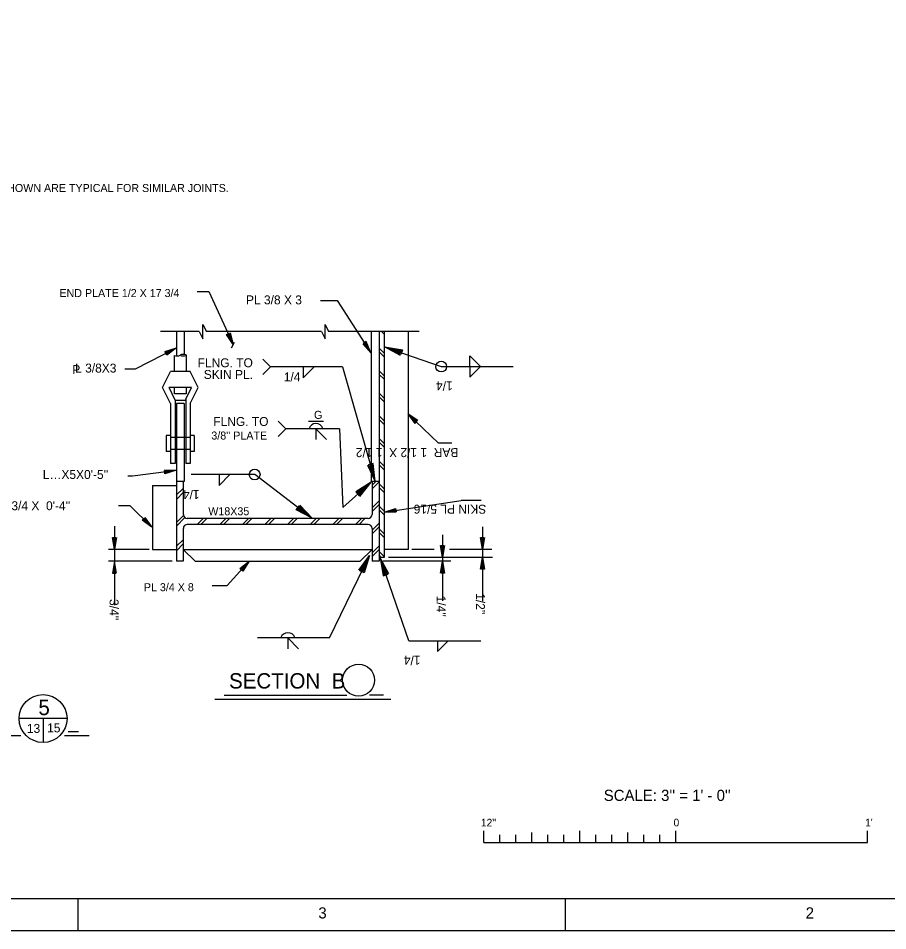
# Model space of a CAD drawing. Extents: x 0 to 13.3, y 0 to 9.3.
# Drawn here: x 5.231 to 9.766, y 0 to 4.76 of the extents above; entities that cross this region are included whole.
import ezdxf

# ---------------------------------------------------------------- set-up
doc = ezdxf.new("R2010")
doc.units = 0
for name, color, linetype in [('Level 1', 7, 'Continuous'), ('Level 10', 7, 'Continuous'), ('Level 13', 7, 'Continuous'), ('Level 2', 7, 'Continuous'), ('Level 25', 7, 'Continuous'), ('Level 3', 7, 'Continuous'), ('Level 44', 7, 'Continuous'), ('Level 50', 7, 'Continuous'), ('Level 7', 7, 'Continuous')]:
    doc.layers.add(name, color=color, linetype=linetype)

msp = doc.modelspace()

# ---------------------------------------------------------------- linework, layer by layer
at = {"layer": 'Level 1'}
for p, q in [((6.1755, 3.1251), (5.9727, 3.1251)), ((7.66, 0.4595), (7.66, 0.522)), ((7.7434, 0.4595), (7.7434, 0.5012)), ((7.8267, 0.4595), (7.8267, 0.5012)), ((7.91, 0.4595), (7.91, 0.5131)), ((7.9934, 0.4595), (7.9934, 0.5012)), ((8.0767, 0.4595), (8.0767, 0.5012)), ((8.16, 0.4595), (8.16, 0.522)), ((8.2434, 0.4595), (8.2434, 0.5012)), ((8.3267, 0.4595), (8.3267, 0.5012)), ((8.41, 0.4595), (8.41, 0.5131)), ((8.4934, 0.4595), (8.4934, 0.5012)), ((8.5767, 0.4595), (8.5767, 0.5012)), ((8.66, 0.4595), (8.66, 0.522)), ((9.66, 0.4595), (9.66, 0.522)), ((7.66, 0.4595), (9.66, 0.4595)), ((5.5417, 0.1667), (5.5417, 0)), ((8.0833, 0.1667), (8.0833, 0))]:
    msp.add_line(p, q, dxfattribs=at)
for points in [[(0, 9.3333), (13.3333, 9.3333), (13.3333, 0), (0, 0)], [(0.5, 9.1667), (13.1667, 9.1667), (13.1667, 0.1667), (0.5, 0.1667)]]:
    msp.add_lwpolyline(points, close=True, dxfattribs=at)
at = {"layer": 'Level 10'}
for points in [[(7.1389, 3.1123), (7.1261, 3.1251)], [(7.1389, 3.0133), (7.1129, 3.0393)], [(7.1389, 2.9944), (7.1129, 3.0204)], [(7.1389, 2.8953), (7.1129, 2.9214)], [(7.1389, 2.8765), (7.1129, 2.9025)], [(7.1389, 2.7774), (7.1129, 2.8035)], [(7.1389, 2.7585), (7.1129, 2.7846)], [(7.1389, 2.6595), (7.1129, 2.6856)], [(7.1389, 2.6406), (7.1129, 2.6667)], [(7.1389, 2.5416), (7.1129, 2.5677)], [(7.1389, 2.5228), (7.1129, 2.5488)], [(7.1389, 2.4237), (7.1128, 2.4498)], [(7.1389, 2.4049), (7.1128, 2.4309)], [(7.0955, 2.3437), (7.0764, 2.3246)], [(7.1129, 2.3423), (7.0764, 2.3057)], [(6.0921, 2.3088), (6.0549, 2.2715)], [(6.0928, 2.2872), (6.0556, 2.25)], [(7.1389, 2.3058), (7.1128, 2.3319)], [(7.1389, 2.2869), (7.1128, 2.313)], [(7.1129, 2.2432), (7.0764, 2.2067)], [(7.1129, 2.2243), (7.0764, 2.1878)], [(7.1389, 2.1879), (7.1128, 2.214)], [(7.1389, 2.169), (7.1128, 2.1951)], [(6.0928, 2.1664), (6.0556, 2.1292)], [(6.1004, 2.1552), (6.0556, 2.1103)], [(6.1953, 2.151), (6.1641, 2.1198)], [(6.2142, 2.151), (6.1829, 2.1198)], [(6.3132, 2.151), (6.282, 2.1198)], [(6.3321, 2.151), (6.3008, 2.1198)], [(6.4311, 2.151), (6.3999, 2.1198)], [(6.45, 2.151), (6.4188, 2.1198)], [(6.549, 2.151), (6.5178, 2.1198)], [(6.5679, 2.151), (6.5367, 2.1198)], [(6.667, 2.151), (6.6357, 2.1198)], [(6.6858, 2.151), (6.6546, 2.1198)], [(6.7849, 2.151), (6.7536, 2.1198)], [(6.8038, 2.151), (6.7725, 2.1198)], [(6.9028, 2.151), (6.8715, 2.1198)], [(6.9216, 2.151), (6.8904, 2.1198)], [(7.0207, 2.151), (6.9894, 2.1198)], [(7.0395, 2.151), (7.0083, 2.1198)], [(7.1129, 2.1253), (7.0764, 2.0888)], [(7.1129, 2.1064), (7.0764, 2.0699)], [(7.1389, 2.07), (7.1128, 2.096)], [(7.1389, 2.0511), (7.1128, 2.0772)], [(6.0921, 2.0417), (6.0549, 2.0045)], [(6.092, 2.0175), (6.0562, 1.9816)], [(7.1129, 2.0074), (7.0764, 1.9709)], [(7.1129, 1.9885), (7.0764, 1.952)], [(7.1389, 1.9521), (7.1128, 1.9782)], [(7.1242, 1.9479), (7.1128, 1.9593)]]:
    msp.add_lwpolyline(points, dxfattribs=at)
at = {"layer": 'Level 13'}
for points in [[(6.1755, 3.1251), (6.1941, 3.0876), (6.1941, 3.1625), (6.2129, 3.1251)], [(6.8123, 3.1251), (6.831, 3.0876), (6.831, 3.1625), (6.8497, 3.1251)]]:
    msp.add_lwpolyline(points, dxfattribs=at)
for centre, radius, start, end in [((6.0583, 3.0369), 0.0383, 249.8081, 296.6071), ((6.0926, 2.9686), 0.0383, 69.8064, 116.6071), ((6.0926, 3.0369), 0.0383, 243.3929, 290.1936), ((6.1052, 3.0027), 0.00188, 290.1936, 69.8064)]:
    msp.add_arc(centre, radius, start, end, dxfattribs=at)
at = {"layer": 'Level 2'}
for p, q in [((6.0556, 3.1251), (6.0556, 3.0023)), ((6.0972, 3.1251), (6.0972, 3.0038)), ((6.8123, 3.1251), (6.2129, 3.1251)), ((7.3214, 3.1251), (6.8497, 3.1251)), ((7.0712, 3.1251), (7.0712, 2.3437)), ((7.1129, 3.1251), (7.1129, 1.9271)), ((7.1389, 3.1251), (7.1389, 1.9479)), ((7.264, 3.1251), (7.264, 1.9896)), ((6.0556, 3.0582), (6.0556, 2.9987)), ((6.0451, 3.001), (6.0451, 2.9171)), ((6.1077, 3.0017), (6.1077, 2.9171)), ((5.9826, 2.8337), (6.0243, 2.9171)), ((6.1285, 2.9171), (6.0243, 2.9171)), ((6.1702, 2.8337), (6.1285, 2.9171)), ((6.0243, 2.7503), (5.9826, 2.8337)), ((6.0501, 2.7686), (6.0176, 2.8337)), ((6.1353, 2.8337), (6.0176, 2.8337)), ((6.0451, 2.8337), (6.0451, 2.8)), ((6.1046, 2.7725), (6.1353, 2.8337)), ((6.1077, 2.8337), (6.1077, 2.8)), ((6.1285, 2.7503), (6.1702, 2.8337)), ((6.1077, 2.8), (6.0464, 2.8)), ((6.0501, 2.7686), (6.0501, 2.4377)), ((6.1046, 2.7725), (6.1046, 2.4377)), ((6.0243, 2.7503), (6.0243, 2.4377)), ((6.0556, 2.7503), (6.0556, 2.3335)), ((6.0972, 2.7503), (6.0556, 2.7503)), ((6.0556, 2.7319), (6.0556, 1.9271)), ((6.0972, 2.7503), (6.0972, 2.3437)), ((6.0972, 2.7334), (6.0972, 2.3437)), ((6.1285, 2.7503), (6.1285, 2.4377)), ((6.0034, 2.5836), (6.0034, 2.5002)), ((6.0243, 2.5836), (6.0034, 2.5836)), ((6.1285, 2.5732), (6.0243, 2.5732)), ((6.1493, 2.5836), (6.1285, 2.5836)), ((6.1493, 2.5836), (6.1493, 2.5002)), ((6.0243, 2.5002), (6.0034, 2.5002)), ((6.1285, 2.5106), (6.0243, 2.5106)), ((6.1493, 2.5002), (6.1285, 2.5002)), ((6.0501, 2.4377), (6.0243, 2.4377)), ((6.1285, 2.4377), (6.1046, 2.4377)), ((6.0972, 2.3437), (6.0556, 2.3437)), ((6.092, 2.3437), (6.092, 2.1719)), ((7.0764, 2.3437), (7.0764, 2.1719)), ((5.9306, 2.3229), (5.9306, 1.9896)), ((7.0555, 2.151), (6.1129, 2.151)), ((6.092, 2.0989), (6.092, 1.9271)), ((7.0555, 2.1198), (6.1129, 2.1198)), ((6.6051, 2.1198), (6.5634, 2.1198)), ((7.0764, 2.0989), (7.0764, 1.9271)), ((7.4008, 1.9896), (7.2829, 1.9896)), ((7.7016, 1.9896), (7.4808, 1.9896)), ((7.7048, 1.9479), (7.162, 1.9479))]:
    msp.add_line(p, q, dxfattribs=at)
at = {"layer": 'Level 25'}
for p, q in [((6.9224, 2.9409), (7.0931, 2.3432)), ((6.0501, 2.7686), (6.1048, 2.7686)), ((6.6259, 2.6182), (6.5861, 2.658)), ((6.6259, 2.6182), (6.5861, 2.5785)), ((6.9062, 2.6182), (6.6259, 2.6182)), ((6.7831, 2.6182), (6.7831, 2.562)), ((6.7831, 2.6182), (6.8391, 2.5622)), ((7.0718, 2.34), (7.0718, 2.34)), ((7.086, 2.3682), (7.086, 2.3682)), ((7.0931, 2.3432), (7.0931, 2.3432)), ((7.0524, 2.3227), (7.0524, 2.3227)), ((7.0626, 1.9575), (7.0626, 1.9575)), ((7.0513, 1.9341), (7.0513, 1.9341)), ((7.2689, 1.5118), (7.1185, 1.9456)), ((7.1185, 1.9456), (7.1185, 1.9456)), ((7.127, 1.921), (7.127, 1.921)), ((6.8544, 1.5273), (6.4794, 1.5273)), ((6.6366, 1.5273), (6.6366, 1.4711)), ((6.6366, 1.5273), (6.6925, 1.4713))]:
    msp.add_line(p, q, dxfattribs=at)
for points in [[(7.0525, 2.4288), (7.0931, 2.3432), (7.0823, 2.4374), (7.0569, 2.4301), (7.086, 2.3682), (7.0786, 2.4321), (7.0623, 2.4275), (7.0791, 2.3922), (7.0749, 2.4269), (7.0682, 2.425), (7.072, 2.4172)], [(7.0125, 2.2661), (7.0718, 2.34), (6.9918, 2.2891), (7.0095, 2.2694), (7.0524, 2.3227), (6.9981, 2.2881), (7.0095, 2.2754), (7.0338, 2.306), (7.0045, 2.287), (7.0091, 2.2818), (7.0145, 2.2886)], [(7.0079, 1.8801), (7.0626, 1.9575), (7.0359, 1.8666), (7.012, 1.8781), (7.0513, 1.9341), (7.0331, 1.8724), (7.0178, 1.8798), (7.0404, 1.9116), (7.0303, 1.8782), (7.024, 1.8812), (7.0291, 1.8882)], [(7.1638, 1.8623), (7.1185, 1.9456), (7.1345, 1.8521), (7.1596, 1.8608), (7.127, 1.921), (7.1379, 1.8576), (7.154, 1.8631), (7.1352, 1.8974), (7.1413, 1.863), (7.1479, 1.8653), (7.1438, 1.8728)]]:
    msp.add_lwpolyline(points, dxfattribs=at)
at = {"layer": 'Level 3'}
for p, q in [((6.3454, 3.0741), (6.3454, 3.0741)), ((6.3527, 3.0584), (6.3527, 3.0584)), ((6.0409, 3.033), (6.0409, 3.033)), ((6.0563, 3.0409), (6.0563, 3.0409)), ((7.061, 3.0296), (7.061, 3.0296)), ((7.0704, 3.015), (7.0704, 3.015)), ((7.1414, 3.0463), (7.1414, 3.0463)), ((7.166, 3.0379), (7.166, 3.0379)), ((7.2622, 2.6973), (7.2622, 2.6973)), ((7.2747, 2.6853), (7.2747, 2.6853)), ((6.0396, 2.3999), (6.0396, 2.3999)), ((6.0568, 2.4022), (6.0568, 2.4022)), ((7.1389, 2.1834), (7.541, 2.2452)), ((7.6449, 2.2452), (7.541, 2.2452)), ((6.7433, 2.1673), (6.7433, 2.1673)), ((6.7639, 2.1515), (6.7639, 2.1515)), ((7.1389, 2.1834), (7.1389, 2.1834)), ((7.1561, 2.1861), (7.1561, 2.1861)), ((5.7328, 2.1099), (5.7328, 1.9896)), ((5.9161, 2.1172), (5.9161, 2.1172)), ((5.9285, 2.1051), (5.9285, 2.1051)), ((7.6516, 2.1065), (7.6516, 1.9896)), ((7.4432, 2.065), (7.4432, 1.9479)), ((7.6516, 2.0096), (7.6516, 1.92)), ((7.6516, 2.0069), (7.6516, 2.0069)), ((5.9131, 1.9896), (5.7013, 1.9896)), ((5.7328, 1.9896), (5.7328, 1.9271)), ((7.4432, 1.9712), (7.4432, 1.9104)), ((7.4432, 1.9652), (7.4432, 1.9652)), ((7.6516, 1.9896), (7.6516, 1.9896)), ((6.0337, 1.9271), (5.7015, 1.9271)), ((5.7328, 1.9271), (5.7328, 1.6983)), ((6.4241, 1.9157), (6.4241, 1.9157)), ((6.4358, 1.9285), (6.4358, 1.9285)), ((7.4872, 1.9271), (7.1331, 1.9271)), ((7.4432, 1.9479), (7.4432, 1.9479)), ((7.4432, 1.9271), (7.4432, 1.7216)), ((7.4432, 1.9271), (7.4432, 1.9271)), ((7.4432, 1.9097), (7.4432, 1.9097)), ((7.6516, 1.9479), (7.6516, 1.7185)), ((7.6516, 1.9479), (7.6516, 1.9479)), ((7.6516, 1.9306), (7.6516, 1.9306)), ((6.2556, 1.2077), (7.1736, 1.2077)), ((6.3055, 1.2285), (6.9453, 1.2285)), ((7.1366, 1.2285), (7.0637, 1.2285)), ((5.4854, 1.1069), (5.2354, 1.1069)), ((5.3604, 1.1069), (5.3604, 0.9819)), ((5.2453, 1.0165), (4.6669, 1.0165)), ((5.6014, 1.0165), (5.4728, 1.0165)), ((5.5452, 1.0374), (5.4922, 1.0374))]:
    msp.add_line(p, q, dxfattribs=at)
for points in [[(6.1636, 3.3347), (6.2255, 3.3347), (6.3527, 3.0584)], [(6.8073, 3.2884), (6.8943, 3.2884), (7.0704, 3.015)], [(6.336, 3.1193), (6.3527, 3.0584), (6.3173, 3.1107), (6.3333, 3.1181), (6.3454, 3.0741), (6.3214, 3.1097), (6.3317, 3.1144), (6.3385, 3.0893), (6.3255, 3.1086), (6.3298, 3.1106), (6.3312, 3.105)], [(7.028, 3.0618), (7.0704, 3.015), (7.0453, 3.073), (7.0305, 3.0634), (7.061, 3.0296), (7.044, 3.0689), (7.0345, 3.0628), (7.052, 3.0436), (7.0426, 3.0649), (7.0387, 3.0624), (7.0426, 3.0581)], [(5.7869, 2.9313), (5.8432, 2.9313), (6.0563, 3.0409)], [(5.9962, 3.0216), (6.0563, 3.0409), (6.0056, 3.0032), (5.9976, 3.0189), (6.0409, 3.033), (6.0065, 3.0074), (6.0013, 3.0175), (6.0261, 3.0254), (6.0073, 3.0116), (6.0052, 3.0157), (6.0107, 3.0174)], [(7.2248, 3.0012), (7.1414, 3.0463), (7.2349, 3.0306), (7.2263, 3.0055), (7.166, 3.0379), (7.2295, 3.0271), (7.224, 3.011), (7.1897, 3.0297), (7.2241, 3.0237), (7.2218, 3.0171), (7.2143, 3.0212)], [(7.4926, 2.5432), (7.4225, 2.5432), (7.2622, 2.6973)], [(7.3143, 2.6616), (7.2622, 2.6973), (7.3, 2.6467), (7.3122, 2.6594), (7.2747, 2.6853), (7.3004, 2.6509), (7.3082, 2.6591), (7.2867, 2.6738), (7.3008, 2.6552), (7.304, 2.6585), (7.2992, 2.6617)], [(5.8033, 2.3725), (5.8277, 2.3725), (6.0568, 2.4022)], [(5.9937, 2.4044), (6.0568, 2.4022), (5.9963, 2.3839), (5.994, 2.4014), (6.0396, 2.3999), (5.9985, 2.3876), (5.9971, 2.3988), (6.0231, 2.3978), (6.0008, 2.3912), (6.0001, 2.3958), (6.0059, 2.3956)], [(5.7544, 2.218), (5.8124, 2.218), (5.9285, 2.1051)], [(6.699, 2.2206), (6.7639, 2.1515), (6.6802, 2.196), (6.6963, 2.217), (6.7433, 2.1673), (6.6864, 2.1975), (6.6968, 2.211), (6.7234, 2.1825), (6.6926, 2.1991), (6.6969, 2.2046), (6.7027, 2.1983)], [(7.2021, 2.1827), (7.1389, 2.1834), (7.199, 2.2031), (7.2017, 2.1856), (7.1561, 2.1861), (7.1969, 2.1994), (7.1986, 2.1882), (7.1726, 2.1886), (7.1947, 2.1957), (7.1954, 2.1911), (7.1897, 2.1912)], [(5.891, 2.1559), (5.9285, 2.1051), (5.8766, 2.1411), (5.8889, 2.1538), (5.9161, 2.1172), (5.8808, 2.1417), (5.8888, 2.1498), (5.9041, 2.1288), (5.8851, 2.1422), (5.8883, 2.1455), (5.8917, 2.1409)], [(7.662, 2.052), (7.6516, 1.9896), (7.6413, 2.052), (7.659, 2.052), (7.6516, 2.0069), (7.6446, 2.0493), (7.656, 2.0493), (7.6516, 2.0236), (7.648, 2.0466), (7.6526, 2.0466), (7.6516, 2.0409)], [(7.4535, 2.0103), (7.4432, 1.9479), (7.4329, 2.0103), (7.4505, 2.0103), (7.4432, 1.9652), (7.4362, 2.0076), (7.4475, 2.0076), (7.4432, 1.9819), (7.4395, 2.0049), (7.4442, 2.0049), (7.4432, 1.9993)], [(6.2426, 1.8007), (6.3203, 1.8007), (6.4358, 1.9285)], [(6.3863, 1.8892), (6.4358, 1.9285), (6.4016, 1.8754), (6.3885, 1.8872), (6.4241, 1.9157), (6.401, 1.8796), (6.3926, 1.8872), (6.413, 1.9033), (6.4003, 1.8838), (6.3968, 1.8869), (6.4014, 1.8905)], [(7.4329, 1.8647), (7.4432, 1.9271), (7.4535, 1.8647), (7.4359, 1.8647), (7.4432, 1.9097), (7.4502, 1.8674), (7.4389, 1.8674), (7.4432, 1.893), (7.4469, 1.87), (7.4422, 1.87), (7.4432, 1.8757)], [(7.6413, 1.8855), (7.6516, 1.9479), (7.662, 1.8855), (7.6443, 1.8855), (7.6516, 1.9306), (7.6586, 1.8882), (7.6473, 1.8882), (7.6516, 1.9139), (7.6553, 1.8909), (7.6506, 1.8909), (7.6516, 1.8965)]]:
    msp.add_lwpolyline(points, dxfattribs=at)
for centre, radius in [((7.0061, 1.3073), 0.0833), ((5.3604, 1.1069), 0.125)]:
    msp.add_circle(centre, radius, dxfattribs=at)
for centre, start, end in [((6.1129, 2.1719), 180, 270), ((7.0555, 2.1719), 270, 0), ((6.1129, 2.0989), 90, 180), ((7.0555, 2.0989), 0, 90)]:
    msp.add_arc(centre, 0.0208, start, end, dxfattribs=at)
at = {"layer": 'Level 44'}
msp.add_line((6.092, 2.3394), (6.0877, 2.3437), dxfattribs=at)
at = {"layer": 'Level 50'}
for p, q in [((6.3429, 3.0414), (6.3597, 3.0698)), ((6.7454, 2.6585), (6.8229, 2.6585)), ((6.9062, 2.6182), (6.9244, 2.2078)), ((6.0972, 2.3437), (6.0556, 2.3437)), ((6.9244, 2.2078), (7.0718, 2.34)), ((7.1129, 2.3437), (7.0712, 2.3437)), ((5.9306, 2.3229), (6.0556, 2.3229)), ((5.7328, 2.0069), (5.7328, 2.0069)), ((5.7328, 1.9896), (5.7328, 1.9896)), ((5.9306, 1.9896), (6.0556, 1.9896)), ((6.092, 1.9896), (7.0764, 1.9896)), ((6.092, 1.9896), (6.1545, 1.9271)), ((6.8544, 1.5273), (7.0626, 1.9575)), ((7.0764, 1.9896), (7.0139, 1.9271)), ((7.264, 1.9896), (7.1389, 1.9896)), ((5.7328, 1.9271), (5.7328, 1.9271)), ((5.7328, 1.9097), (5.7328, 1.9097)), ((6.092, 1.9271), (6.0556, 1.9271)), ((6.1545, 1.9271), (7.0139, 1.9271)), ((7.1129, 1.9271), (7.0764, 1.9271)), ((7.1389, 1.9479), (7.1129, 1.9479))]:
    msp.add_line(p, q, dxfattribs=at)
for points in [[(5.7431, 2.0519), (5.7328, 1.9896), (5.7225, 2.0519), (5.7401, 2.0519), (5.7328, 2.0069), (5.7258, 2.0492), (5.7371, 2.0492), (5.7328, 2.0236), (5.7291, 2.0466), (5.7338, 2.0466), (5.7328, 2.0409)], [(5.7431, 1.8647), (5.7328, 1.9271), (5.7225, 1.8647), (5.7401, 1.8647), (5.7328, 1.9097), (5.7258, 1.8674), (5.7371, 1.8674), (5.7328, 1.8931), (5.7291, 1.8701), (5.7338, 1.8701), (5.7328, 1.8757)]]:
    msp.add_lwpolyline(points, dxfattribs=at)
for centre in [(6.7839, 2.6074), (6.6373, 1.5165)]:
    msp.add_arc(centre, 0.0383, 20.1021, 161.1053, dxfattribs=at)
at = {"layer": 'Level 7'}
for p, q in [((7.1389, 3.0454), (7.4369, 2.9429)), ((6.5472, 2.9409), (6.5073, 2.9808)), ((7.586, 2.9986), (7.6419, 2.9427)), ((7.586, 2.9423), (7.586, 2.9986)), ((6.5472, 2.9409), (6.5073, 2.9011)), ((6.9224, 2.9409), (6.5472, 2.9409)), ((6.7173, 2.9409), (6.7173, 2.8846)), ((6.7173, 2.8846), (6.7732, 2.9405)), ((7.4369, 2.9429), (7.8123, 2.9429)), ((7.586, 2.9435), (7.586, 2.8872)), ((7.586, 2.8872), (7.6419, 2.9431)), ((6.4642, 2.3797), (6.1336, 2.3797)), ((6.279, 2.3797), (6.279, 2.3234)), ((6.279, 2.3234), (6.3349, 2.3793)), ((6.7633, 2.151), (6.4642, 2.3797)), ((7.2689, 1.5118), (7.6442, 1.5118)), ((7.418, 1.5124), (7.418, 1.4561)), ((7.418, 1.4561), (7.4739, 1.512))]:
    msp.add_line(p, q, dxfattribs=at)
for centre in [(7.4369, 2.9429), (6.4642, 2.3797)]:
    msp.add_circle(centre, 0.0281, dxfattribs=at)

# ---------------------------------------------------------------- texts
at = {"layer": 'Level 1'}
for s, height, p in [("SCALE: 3'' = 1' - 0''", 0.058332, (8.2845, 0.6771)), ("12''", 0.04, (7.6437, 0.544)), ('0', 0.04, (8.6485, 0.5444)), ("1'", 0.04, (9.6474, 0.5444)), ('3', 0.0584, (6.7961, 0.0639)), ('2', 0.0584, (9.3378, 0.0638))]:
    msp.add_text(s, height=height, dxfattribs=at).set_placement(p)
at = {"layer": 'Level 3'}
for s, height, p in [('PL 3/8 X 3', 0.04669, (6.419, 3.2675)), ('L 3/8X3 ', 0.04667, (5.528, 2.9117)), ('FLNG. TO', 0.04669, (6.1668, 2.9395)), ('P', 0.0467, (5.5131, 2.9041)), ('SKIN PL.', 0.04669, (6.1986, 2.8786)), ('1/4', 0.04669, (6.6159, 2.8655)), ('FLNG. TO', 0.04669, (6.2483, 2.6331)), ("L…X5X0'-5''", 0.046677, (5.3592, 2.3567)), ("BAR  1 3/4 X  1 3/4 X  0'-4''", 0.046688, (4.7479, 2.1936)), ('SECTION  B', 0.08, (6.3305, 1.2636)), ('5', 0.08, (5.3363, 1.1248)), ('13', 0.04679, (5.276, 1.0319)), ('15', 0.04679, (5.3817, 1.0347))]:
    msp.add_text(s, height=height, dxfattribs=at).set_placement(p)
for s, height, rotation, p in [('1/4', 0.04669, 180, (7.4968, 2.8653)), ('BAR  1 1/2 X  1 1/2', 0.04669, 180, (7.5264, 2.5175)), ('1/4', 0.04669, 180, (6.1767, 2.2989)), ('SKIN PL 5/16', 0.04669, 180, (7.6718, 2.2223)), ("3/4''", 0.04668, 270, (5.7076, 1.7303)), ("1/4''", 0.04669, 270, (7.4132, 1.7483)), ("1/2''", 0.04669, 270, (7.6181, 1.7607)), ('1/4', 0.04669, 180, (7.3288, 1.4343))]:
    msp.add_text(s, height=height, rotation=rotation, dxfattribs=at).set_placement(p)
at = {"layer": 'Level 44'}
msp.add_text('WELDS SHOWN ARE TYPICAL FOR SIMILAR JOINTS.', height=0.041698, dxfattribs=at).set_placement((4.9225, 3.8537))
at = {"layer": 'Level 50'}
for s, height, p in [('END PLATE 1/2 X 17 3/4', 0.041698, (5.4459, 3.3057)), ('G', 0.0417, (6.7735, 2.6703)), ("3/8'' PLATE", 0.041698, (6.2382, 2.5624)), ('W18X35', 0.0417, (6.2222, 2.1674)), ('PL 3/4 X 8', 0.0417, (5.8862, 1.7713))]:
    msp.add_text(s, height=height, dxfattribs=at).set_placement(p)

doc.saveas('drawing.dxf')
